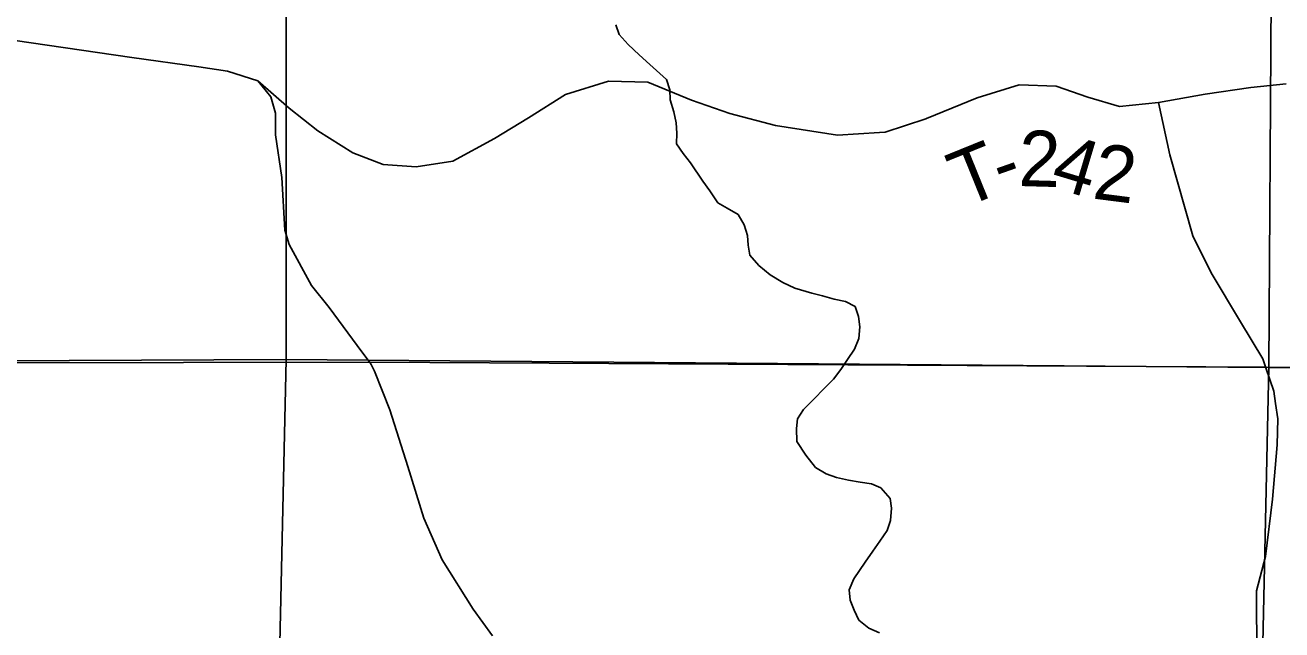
# Model space of a CAD drawing. Extents: x 0 to 34, y 0 to 22.
# Drawn here: x 3.273 to 4.552, y 18.878 to 19.493 of the extents above; entities that cross this region are included whole.
import ezdxf

# ---------------------------------------------------------------- set-up
doc = ezdxf.new("R2010")
doc.units = 0
for name, color, linetype in [('Default', 7, 'Continuous'), ('GM_X_Minor_River', 7, 'Continuous'), ('GM_X_Section', 7, 'Continuous'), ('GM_X_Township_Road', 7, 'Continuous'), ('GM_X_Township_Road_Text', 7, 'Continuous')]:
    doc.layers.add(name, color=color, linetype=linetype)

msp = doc.modelspace()

# ---------------------------------------------------------------- linework, layer by layer
at = {"layer": 'Default'}
for p, q in [((3.624, 19.1497), (2.7675, 19.1488)), ((2.7675, 19.1488), (3.624, 19.1497)), ((4.5355, 19.1447), (3.624, 19.1497)), ((3.624, 19.1497), (4.5355, 19.1447)), ((5.3758, 19.1372), (4.5355, 19.1447)), ((4.5355, 19.1447), (5.3758, 19.1372))]:
    msp.add_line(p, q, dxfattribs=at)
at = {"layer": 'GM_X_Minor_River'}
for p, q in [((3.8774, 19.483), (3.874, 19.4928)), ((3.8868, 19.473), (3.8774, 19.483)), ((3.8978, 19.4624), (3.8868, 19.473)), ((3.9088, 19.4524), (3.8978, 19.4624)), ((3.9256, 19.4374), (3.9088, 19.4524)), ((3.929, 19.4268), (3.9256, 19.4374)), ((3.9293, 19.4166), (3.929, 19.4268)), ((3.9331, 19.4045), (3.9293, 19.4166)), ((3.9357, 19.3932), (3.9331, 19.4045)), ((3.9364, 19.3826), (3.9357, 19.3932)), ((3.936, 19.3719), (3.9364, 19.3826)), ((3.9428, 19.3622), (3.936, 19.3719)), ((3.9503, 19.3526), (3.9428, 19.3622)), ((3.9627, 19.3339), (3.9503, 19.3526)), ((3.9698, 19.3239), (3.9627, 19.3339)), ((3.9778, 19.312), (3.9698, 19.3239)), ((3.9875, 19.3066), (3.9778, 19.312)), ((3.9987, 19.3001), (3.9875, 19.3066)), ((4.0047, 19.2896), (3.9987, 19.3001)), ((4.0081, 19.2787), (4.0047, 19.2896)), ((4.0088, 19.2688), (4.0081, 19.2787)), ((4.0106, 19.2586), (4.0088, 19.2688)), ((4.0197, 19.2483), (4.0106, 19.2586)), ((4.0314, 19.2387), (4.0197, 19.2483)), ((4.0442, 19.2308), (4.0314, 19.2387)), ((4.0565, 19.2251), (4.0442, 19.2308)), ((4.0738, 19.2199), (4.0565, 19.2251)), ((4.0845, 19.2172), (4.0738, 19.2199)), ((4.0964, 19.2138), (4.0845, 19.2172)), ((4.1079, 19.2115), (4.0964, 19.2138)), ((4.1176, 19.2065), (4.1079, 19.2115)), ((4.1213, 19.1963), (4.1176, 19.2065)), ((4.1224, 19.1857), (4.1213, 19.1963)), ((4.117, 19.1631), (4.1216, 19.1739)), ((4.1216, 19.1739), (4.1224, 19.1857)), ((4.1098, 19.1526), (4.117, 19.1631)), ((4.1032, 19.1425), (4.1098, 19.1526)), ((4.0956, 19.1324), (4.1032, 19.1425)), ((4.076, 19.1127), (4.086, 19.1226)), ((4.086, 19.1226), (4.0956, 19.1324)), ((4.0653, 19.1018), (4.076, 19.1127)), ((4.0592, 19.0921), (4.0653, 19.1018)), ((4.058, 19.0825), (4.0592, 19.0921)), ((4.0584, 19.0692), (4.058, 19.0825)), ((4.0675, 19.0554), (4.0584, 19.0692)), ((4.0774, 19.0428), (4.0675, 19.0554)), ((4.0883, 19.0363), (4.0774, 19.0428)), ((4.0987, 19.0324), (4.0883, 19.0363)), ((4.1109, 19.0298), (4.0987, 19.0324)), ((4.1228, 19.0279), (4.1109, 19.0298)), ((4.1342, 19.026), (4.1228, 19.0279)), ((4.1439, 19.0221), (4.1342, 19.026)), ((4.1533, 19.0113), (4.1439, 19.0221)), ((4.1548, 19.0015), (4.1533, 19.0113)), ((4.1537, 18.9889), (4.1548, 19.0015)), ((4.1502, 18.9785), (4.1537, 18.9889)), ((4.1429, 18.9677), (4.1502, 18.9785)), ((4.128, 18.9466), (4.1356, 18.9575)), ((4.1356, 18.9575), (4.1429, 18.9677)), ((4.1163, 18.9295), (4.128, 18.9466)), ((4.1117, 18.9184), (4.1163, 18.9295)), ((4.1125, 18.9077), (4.1117, 18.9184)), ((4.1166, 18.8976), (4.1125, 18.9077)), ((4.1215, 18.8875), (4.1166, 18.8976)), ((4.1316, 18.8794), (4.1215, 18.8875)), ((4.1424, 18.8745), (4.1316, 18.8794))]:
    msp.add_line(p, q, dxfattribs=at)
at = {"layer": 'GM_X_Section'}
for p, q in [((3.5383, 20.1501), (3.5387, 19.1524)), ((3.5387, 19.1524), (3.5383, 20.1501)), ((4.5449, 20.1449), (4.5388, 19.1444)), ((4.5388, 19.1444), (4.5449, 20.1449)), ((3.5387, 19.1524), (2.5274, 19.148)), ((2.5274, 19.148), (3.5387, 19.1524)), ((3.5387, 19.1524), (3.5154, 18.1224)), ((3.5154, 18.1224), (3.5387, 19.1524)), ((4.5388, 19.1444), (3.5387, 19.1524)), ((3.5387, 19.1524), (4.5388, 19.1444)), ((4.5388, 19.1444), (4.5166, 18.1148)), ((4.5166, 18.1148), (4.5388, 19.1444)), ((5.5458, 19.1336), (4.5388, 19.1444)), ((4.5388, 19.1444), (5.5458, 19.1336))]:
    msp.add_line(p, q, dxfattribs=at)
at = {"layer": 'GM_X_Township_Road'}
for p, q in [((3.1549, 19.4923), (3.3814, 19.4598)), ((3.3814, 19.4598), (3.4499, 19.4503)), ((3.4499, 19.4503), (3.4788, 19.4459)), ((3.4788, 19.4459), (3.5099, 19.4359)), ((3.5099, 19.4359), (3.5418, 19.4081)), ((3.5231, 19.4198), (3.5099, 19.4359)), ((3.823, 19.422), (3.8666, 19.4357)), ((3.8666, 19.4357), (3.9068, 19.4345)), ((3.9068, 19.4345), (3.9511, 19.4163)), ((4.2418, 19.4186), (4.2847, 19.4319)), ((4.2847, 19.4319), (4.3222, 19.4305)), ((4.3222, 19.4305), (4.3545, 19.4194)), ((4.5205, 19.429), (4.5563, 19.4329)), ((3.5277, 19.4029), (3.5231, 19.4198)), ((3.7854, 19.3983), (3.823, 19.422)), ((3.9511, 19.4163), (3.9902, 19.4028)), ((4.1905, 19.3977), (4.2418, 19.4186)), ((4.3545, 19.4194), (4.3867, 19.4098)), ((4.4266, 19.4138), (4.4739, 19.4224)), ((4.4739, 19.4224), (4.5205, 19.429)), ((3.5418, 19.4081), (3.5708, 19.385)), ((4.3867, 19.4098), (4.4266, 19.4138)), ((4.438, 19.3608), (4.4266, 19.4138)), ((3.5279, 19.3809), (3.5277, 19.4029)), ((3.7508, 19.3774), (3.7854, 19.3983)), ((3.9902, 19.4028), (4.0365, 19.3905)), ((4.1484, 19.3837), (4.1896, 19.3974)), ((4.1896, 19.3974), (4.1905, 19.3977)), ((3.5341, 19.3377), (3.5279, 19.3809)), ((3.5708, 19.385), (3.6066, 19.3627)), ((4.0365, 19.3905), (4.0998, 19.3807)), ((4.0998, 19.3807), (4.1426, 19.3833)), ((4.1426, 19.3833), (4.1484, 19.3837)), ((3.7083, 19.3543), (3.7508, 19.3774)), ((3.6066, 19.3627), (3.6374, 19.3508)), ((3.6708, 19.3485), (3.7083, 19.3543)), ((4.4614, 19.2783), (4.438, 19.3608)), ((3.6374, 19.3508), (3.6708, 19.3485)), ((3.5372, 19.2839), (3.5341, 19.3377)), ((3.5417, 19.2696), (3.5372, 19.2839)), ((4.4801, 19.2408), (4.4614, 19.2783)), ((3.5643, 19.2279), (3.5417, 19.2696)), ((4.5099, 19.1908), (4.4801, 19.2408)), ((3.5824, 19.2053), (3.5643, 19.2279)), ((3.6155, 19.1603), (3.5824, 19.2053)), ((4.5327, 19.1531), (4.5099, 19.1908)), ((3.6242, 19.1492), (3.6155, 19.1603)), ((3.6251, 19.1475), (3.6242, 19.1492)), ((4.5357, 19.1442), (4.5327, 19.1531)), ((3.6286, 19.1408), (3.6251, 19.1475)), ((3.6442, 19.1012), (3.6286, 19.1408)), ((4.5437, 19.1202), (4.5357, 19.1442)), ((4.5456, 19.1077), (4.5437, 19.1202)), ((3.6623, 19.0436), (3.6442, 19.1012)), ((4.5479, 19.0923), (4.5456, 19.1077)), ((4.5472, 19.0657), (4.5479, 19.0923)), ((4.5425, 19.0104), (4.5472, 19.0657)), ((3.6789, 18.9911), (3.6623, 19.0436)), ((4.5352, 18.9523), (4.5425, 19.0104)), ((3.6974, 18.9488), (3.6789, 18.9911)), ((3.7288, 18.8988), (3.6974, 18.9488)), ((4.5262, 18.9174), (4.5352, 18.9523)), ((4.5268, 18.8092), (4.5262, 18.9174)), ((3.7486, 18.8714), (3.7288, 18.8988))]:
    msp.add_line(p, q, dxfattribs=at)

# ---------------------------------------------------------------- texts
at = {"layer": 'GM_X_Township_Road_Text'}
for s, rotation, p in [('2', 358.3918, (4.2836, 19.329)), ('T', 22.064, (4.2282, 19.3064)), ('4', 343.2619, (4.3146, 19.3287)), ('2', 352.7597, (4.3582, 19.3164)), ('-', 19.4002, (4.267, 19.3221))]:
    msp.add_text(s, height=0.0568, rotation=rotation, dxfattribs=at).set_placement(p)

doc.saveas('drawing.dxf')
